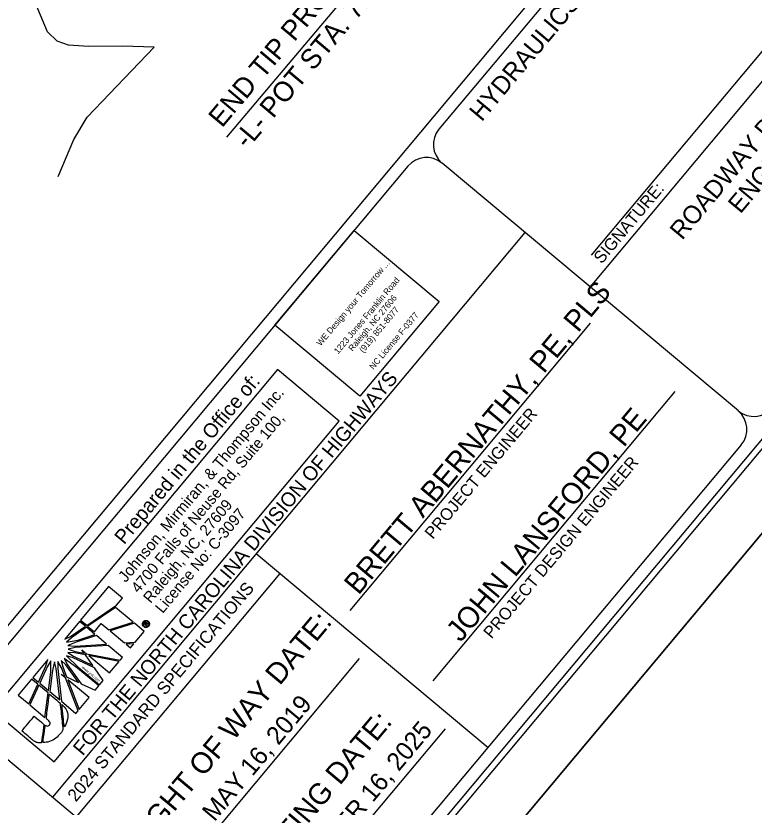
# Model space of a CAD drawing. Extents: x 555292 to 2368606, y 503623 to 1171444.
# Drawn here: x 2361691 to 2363221, y 1163175 to 1164815 of the extents above; entities that cross this region are included whole.
import ezdxf

# ---------------------------------------------------------------- set-up
doc = ezdxf.new("R2010")
doc.units = 0
for name, color, linetype in [('Old_Level_48', 7, 'Continuous'), ('Prop DSN Text', 7, 'Continuous'), ('Prop Horizontal Alignment Station Label', 7, 'Continuous'), ('Sheet Cutting Line CELL', 7, 'Continuous'), ('Sheet Data Field CELL', 7, 'Continuous'), ('Sheet Plot Border Inside CELL', 7, 'Continuous'), ('Sheet Plot Border Outside CELL', 7, 'Continuous'), ('Sheet Title CELL', 7, 'Continuous')]:
    doc.layers.add(name, color=color, linetype=linetype)

msp = doc.modelspace()

# ---------------------------------------------------------------- linework, layer by layer
at = {"layer": 'Old_Level_48'}
msp.add_lwpolyline([(2361778.9, 1164481.9), (2361811.7, 1164558.5), (2361839.3, 1164604.9), (2361978.2, 1164750.1), (2361911.7, 1164752.1), (2361841.9, 1164751.4), (2361800.9, 1164754.1), (2361776.9, 1164762.2), (2361757, 1164781.8), (2361660.4, 1165011.9), (2362007.6, 1164911.3), (2362056.6, 1165270.2), (2361940.1, 1165388.6), (2361913.2, 1165415.1), (2361872.2, 1165436.7), (2361834, 1165456.3)], dxfattribs=at)
at = {"layer": 'Prop DSN Text'}
for p, q in [((2361883.6, 1163632.3), (2361825.6, 1163562.8)), ((2361912.1, 1163608.6), (2361883.6, 1163632.3)), ((2361899.7, 1163593.8), (2361912.1, 1163608.6)), ((2361838.7, 1163551.9), (2361899.7, 1163593.8)), ((2361898.1, 1163589.2), (2361840.7, 1163550.2)), ((2361934.6, 1163558.8), (2361898.1, 1163589.2)), ((2361823.6, 1163560.1), (2361792.8, 1163523.6)), ((2361835.5, 1163550.2), (2361823.6, 1163560.1)), ((2361825.6, 1163562.8), (2361838.3, 1163552.2)), ((2361854.2, 1163538.9), (2361868.4, 1163555.9)), ((2361868.4, 1163555.9), (2361884.2, 1163542.6)), ((2361884.2, 1163542.6), (2361934.6, 1163558.8)), ((2361937.1, 1163556.6), (2361887, 1163540.4)), ((2361957.6, 1163539.5), (2361937.1, 1163556.6)), ((2361955.5, 1163559.6), (2361956.5, 1163558.7)), ((2361956.5, 1163558.7), (2361955.5, 1163559.6)), ((2361956.7, 1163555), (2361958.4, 1163557.1)), ((2361961.8, 1163550.8), (2361956.7, 1163555)), ((2361958.4, 1163557.1), (2361958.7, 1163557.4)), ((2361958.4, 1163557.1), (2361959.4, 1163556.3)), ((2361959.4, 1163556.3), (2361958.4, 1163557.1)), ((2361959.4, 1163556.3), (2361958.6, 1163555.4)), ((2361958.6, 1163555.4), (2361959.8, 1163554.4)), ((2361959.5, 1163556.4), (2361959.4, 1163556.3)), ((2361959.8, 1163554.4), (2361960.6, 1163555.3)), ((2361960.6, 1163555.3), (2361961.5, 1163554.5)), ((2361961.5, 1163554.5), (2361960.6, 1163555.3)), ((2361960.6, 1163555.3), (2361960.6, 1163555.3)), ((2361961.5, 1163554.5), (2361960.8, 1163553.6)), ((2361960.8, 1163553.6), (2361962.7, 1163552)), ((2361961.6, 1163554.6), (2361961.5, 1163554.5)), ((2361804.9, 1163529.2), (2361835.5, 1163550.2)), ((2361838, 1163548.1), (2361806.6, 1163526.3)), ((2361855.3, 1163533.3), (2361838, 1163548.1)), ((2361838.3, 1163552.2), (2361838.7, 1163551.9)), ((2361840.7, 1163550.2), (2361840.9, 1163550)), ((2361840.9, 1163550), (2361854.2, 1163538.9)), ((2361887, 1163540.4), (2361916.5, 1163515.7)), ((2361938.9, 1163517.1), (2361957.6, 1163539.5)), ((2361962.7, 1163552), (2361961.8, 1163550.8)), ((2361965.5, 1163551.2), (2361965.5, 1163551.3)), ((2361965.5, 1163551.2), (2361966.6, 1163550.3)), ((2361966.6, 1163550.3), (2361965.5, 1163551.2)), ((2361966.6, 1163550.4), (2361966.6, 1163550.3)), ((2361792.8, 1163523.6), (2361804.9, 1163529.2)), ((2361806.6, 1163526.3), (2361796.7, 1163517.2)), ((2361796.7, 1163517.2), (2361819.6, 1163521.6)), ((2361858.3, 1163530.8), (2361816.5, 1163517.5)), ((2361819.6, 1163521.6), (2361855.3, 1163533.3)), ((2361879.4, 1163513.1), (2361858.3, 1163530.8)), ((2361816.5, 1163517.5), (2361799.4, 1163510)), ((2361799.4, 1163510), (2361813.9, 1163508.8)), ((2361814.3, 1163506), (2361800.2, 1163502.8)), ((2361813.9, 1163508.8), (2361879.4, 1163513.1)), ((2361882.9, 1163510.3), (2361814.3, 1163506)), ((2361912.5, 1163485.5), (2361882.9, 1163510.3)), ((2361916.5, 1163515.7), (2361938.9, 1163517.1)), ((2361936.2, 1163513.8), (2361919.8, 1163513)), ((2361919.8, 1163513), (2361929, 1163505.2)), ((2361929, 1163505.2), (2361936.2, 1163513.8)), ((2361796.3, 1163489.2), (2361820.9, 1163465.7)), ((2361810.5, 1163484.7), (2361796.3, 1163489.2)), ((2361799.2, 1163495.7), (2361810.7, 1163487.9)), ((2361813, 1163495), (2361799.2, 1163495.7)), ((2361800.2, 1163502.8), (2361814.1, 1163498)), ((2361810.7, 1163487.9), (2361851.3, 1163468.6)), ((2361835.6, 1163490.7), (2361813, 1163495)), ((2361814.1, 1163498), (2361833.2, 1163494.1)), ((2361833.2, 1163494.1), (2361828.1, 1163501.3)), ((2361828.1, 1163501.3), (2361837.7, 1163493.2)), ((2361851.3, 1163468.6), (2361835.6, 1163490.7)), ((2361837.7, 1163493.2), (2361907.7, 1163479.7)), ((2361905.2, 1163477.1), (2361842.5, 1163489.3)), ((2361842.5, 1163489.3), (2361885.5, 1163453.4)), ((2361757.7, 1163481.5), (2361726.6, 1163444.3)), ((2361753.9, 1163468.5), (2361757.7, 1163481.5)), ((2361764.2, 1163478.2), (2361756.5, 1163466.4)), ((2361763.9, 1163455.3), (2361764.2, 1163478.2)), ((2361771.6, 1163476.7), (2361767.5, 1163458.8)), ((2361775.2, 1163462.8), (2361771.6, 1163476.7)), ((2361778.8, 1163477.2), (2361778.2, 1163462.8)), ((2361786, 1163464.3), (2361778.8, 1163477.2)), ((2361785.7, 1163479.5), (2361788.6, 1163465.9)), ((2361795.1, 1163470), (2361785.7, 1163479.5)), ((2361819, 1163463.4), (2361791.7, 1163483.7)), ((2361791.7, 1163483.7), (2361798.5, 1163470.3)), ((2361854.7, 1163463.9), (2361810.5, 1163484.7)), ((2361885.5, 1163453.4), (2361905.2, 1163477.1)), ((2361907.7, 1163479.7), (2361912.5, 1163485.5)), ((2361738.4, 1163434.4), (2361753.9, 1163468.5)), ((2361756.5, 1163466.4), (2361741, 1163432.3)), ((2361758.9, 1163417.3), (2361763.9, 1163455.3)), ((2361767.5, 1163458.8), (2361761.8, 1163414.9)), ((2361782.4, 1163397.7), (2361775.2, 1163462.8)), ((2361778.2, 1163462.8), (2361785.9, 1163394.8)), ((2361792.8, 1163446.9), (2361786, 1163464.3)), ((2361788.6, 1163465.9), (2361796.7, 1163445.2)), ((2361821, 1163433.9), (2361795.1, 1163470)), ((2361798.5, 1163470.3), (2361826.5, 1163431.2)), ((2361863.1, 1163426.6), (2361819, 1163463.4)), ((2361820.9, 1163465.7), (2361865, 1163428.9)), ((2361872.7, 1163438.1), (2361854.7, 1163463.9)), ((2361723.9, 1163440.7), (2361696.3, 1163407.7)), ((2361736.7, 1163430.1), (2361723.9, 1163440.7)), ((2361726.6, 1163444.3), (2361738.4, 1163434.4)), ((2361794.2, 1163443), (2361785.5, 1163450.2)), ((2361785.5, 1163450.2), (2361792.8, 1163446.9)), ((2361820.5, 1163375.2), (2361794.2, 1163443)), ((2361796.7, 1163445.2), (2361821, 1163433.9)), ((2361843.2, 1163402.4), (2361798.9, 1163439)), ((2361798.9, 1163439), (2361822.6, 1163377.8)), ((2361718.2, 1163389.4), (2361736.7, 1163430.1)), ((2361739.1, 1163428.1), (2361720.7, 1163387.3)), ((2361758.2, 1163412.1), (2361739.1, 1163428.1)), ((2361741, 1163432.3), (2361758.9, 1163417.3)), ((2361826.5, 1163431.2), (2361855.5, 1163417.5)), ((2361855.5, 1163417.5), (2361863.1, 1163426.6)), ((2361865, 1163428.9), (2361872.7, 1163438.1)), ((2361696.3, 1163407.7), (2361718.2, 1163389.4)), ((2361751.6, 1163361.5), (2361758.2, 1163412.1)), ((2361761.8, 1163414.9), (2361782.4, 1163397.7)), ((2361785.9, 1163394.8), (2361815.9, 1163369.7)), ((2361822.6, 1163377.8), (2361843.2, 1163402.4)), ((2361720.7, 1163387.3), (2361751.6, 1163361.5)), ((2361815.9, 1163369.7), (2361820.5, 1163375.2))]:
    msp.add_line(p, q, dxfattribs=at)
for points in [[(2362568.3, 1164223), (2362403.9, 1164026.5), (2362228, 1164173.7), (2362392.4, 1164370.2)], [(2361770.7, 1163269.5), (2362361.1, 1163975.3), (2362233.7, 1164081.9), (2361643.3, 1163376.1)]]:
    msp.add_lwpolyline(points, close=True, dxfattribs=at)
for points in [[(2361883.6, 1163632.3), (2361825.6, 1163562.8), (2361838.3, 1163552.2), (2361838.7, 1163551.9), (2361899.7, 1163593.8), (2361912.1, 1163608.6), (2361883.6, 1163632.3)], [(2361840.7, 1163550.2), (2361840.9, 1163550), (2361854.2, 1163538.9), (2361868.4, 1163555.9), (2361884.2, 1163542.6), (2361934.6, 1163558.8), (2361898.1, 1163589.2), (2361840.7, 1163550.2)], [(2361804.9, 1163529.2), (2361835.5, 1163550.2), (2361823.6, 1163560.1), (2361792.8, 1163523.6), (2361804.9, 1163529.2)], [(2361887, 1163540.4), (2361916.5, 1163515.7), (2361938.9, 1163517.1), (2361957.6, 1163539.5), (2361937.1, 1163556.6), (2361887, 1163540.4), (2361887, 1163540.4)], [(2361964.1, 1163556.1), (2361964.4, 1163555.9), (2361964.6, 1163555.7), (2361964.8, 1163555.6), (2361965.5, 1163555.3), (2361964.6, 1163554.2)], [(2361796.7, 1163517.2), (2361819.6, 1163521.6), (2361855.3, 1163533.3), (2361838, 1163548.1), (2361806.6, 1163526.3), (2361796.7, 1163517.2)], [(2361799.4, 1163510), (2361813.9, 1163508.8), (2361879.4, 1163513.1), (2361858.3, 1163530.8), (2361816.5, 1163517.5), (2361799.4, 1163510)], [(2361800.2, 1163502.8), (2361814.1, 1163498), (2361833.2, 1163494.1), (2361828.1, 1163501.3), (2361837.7, 1163493.2), (2361907.7, 1163479.7), (2361912.5, 1163485.5), (2361882.9, 1163510.3), (2361814.3, 1163506), (2361800.2, 1163502.8)], [(2361929, 1163505.2), (2361929, 1163505.2), (2361936.2, 1163513.8), (2361919.8, 1163513), (2361929, 1163505.2)], [(2361796.3, 1163489.2), (2361820.9, 1163465.7), (2361865, 1163428.9), (2361872.7, 1163438.1), (2361854.7, 1163463.9), (2361810.5, 1163484.7), (2361796.3, 1163489.2)], [(2361799.2, 1163495.7), (2361810.7, 1163487.9), (2361851.3, 1163468.6), (2361835.6, 1163490.7), (2361813, 1163495), (2361799.2, 1163495.7)], [(2361885.5, 1163453.4), (2361905.2, 1163477.1), (2361842.5, 1163489.3), (2361885.5, 1163453.4)], [(2361753.9, 1163468.5), (2361757.7, 1163481.5), (2361726.6, 1163444.3), (2361738.4, 1163434.4), (2361753.9, 1163468.5)], [(2361741, 1163432.3), (2361758.9, 1163417.3), (2361763.9, 1163455.3), (2361764.2, 1163478.2), (2361756.5, 1163466.4), (2361741, 1163432.3)], [(2361761.8, 1163414.9), (2361782.4, 1163397.7), (2361775.2, 1163462.8), (2361771.6, 1163476.7), (2361767.5, 1163458.8), (2361761.8, 1163414.9)], [(2361778.8, 1163477.2), (2361778.2, 1163462.8), (2361785.9, 1163394.8), (2361815.9, 1163369.7), (2361820.5, 1163375.2), (2361794.2, 1163443), (2361785.5, 1163450.2), (2361792.8, 1163446.9), (2361786, 1163464.3), (2361778.8, 1163477.2)], [(2361785.7, 1163479.5), (2361788.6, 1163465.9), (2361796.7, 1163445.2), (2361821, 1163433.9), (2361795.1, 1163470), (2361785.7, 1163479.5)], [(2361798.5, 1163470.3), (2361826.5, 1163431.2), (2361855.5, 1163417.5), (2361863.1, 1163426.6), (2361819, 1163463.4), (2361791.7, 1163483.7), (2361798.5, 1163470.3)], [(2361718.2, 1163389.4), (2361736.7, 1163430.1), (2361723.9, 1163440.7), (2361696.3, 1163407.7), (2361718.2, 1163389.4)], [(2361822.6, 1163377.8), (2361843.2, 1163402.4), (2361798.9, 1163439), (2361822.6, 1163377.8)], [(2361751.6, 1163361.5), (2361758.2, 1163412.1), (2361739.1, 1163428.1), (2361720.7, 1163387.3), (2361751.6, 1163361.5)]]:
    msp.add_lwpolyline(points, dxfattribs=at)
for points, degree in [([(2361966.6, 1163550.3), (2361965.3, 1163548.8), (2361963.6, 1163547.9), (2361961.6, 1163547.7), (2361959.6, 1163547.5), (2361957.9, 1163548.1), (2361956.3, 1163549.4), (2361954.7, 1163550.7), (2361953.9, 1163552.4), (2361953.8, 1163554.3), (2361953.6, 1163556.3), (2361954.2, 1163558), (2361955.5, 1163559.6)], 3), ([(2361956.5, 1163558.7), (2361955.5, 1163557.5), (2361955, 1163556.1), (2361955.1, 1163554.5), (2361955.3, 1163552.9), (2361956, 1163551.5), (2361957.2, 1163550.5), (2361958.5, 1163549.4), (2361959.9, 1163549), (2361961.5, 1163549.1), (2361963.1, 1163549.3), (2361964.4, 1163550), (2361965.5, 1163551.2)], 3), ([(2361955.5, 1163559.6), (2361956.8, 1163561.2), (2361958.4, 1163562), (2361960.4, 1163562.2), (2361962.3, 1163562.5), (2361964.1, 1163561.9), (2361965.7, 1163560.6)], 3), ([(2361965.5, 1163551.3), (2361966.5, 1163552.5), (2361967, 1163553.9), (2361966.9, 1163555.5), (2361966.7, 1163557.1), (2361966, 1163558.5), (2361964.8, 1163559.5), (2361963.5, 1163560.6), (2361962, 1163561), (2361960.4, 1163560.9), (2361958.9, 1163560.7), (2361957.6, 1163560), (2361956.5, 1163558.7)], 3), ([(2361958.7, 1163557.4), (2361959.8, 1163558.7), (2361960.8, 1163558.9), (2361961.8, 1163558.1), (2361962.3, 1163557.7), (2361962.5, 1163557.2), (2361962.4, 1163556.6)], 3), ([(2361960.6, 1163555.3), (2361961.3, 1163556.1), (2361961.3, 1163556.6), (2361960.9, 1163557), (2361960.6, 1163557.3), (2361960.1, 1163557.1), (2361959.5, 1163556.4)], 3), ([(2361962.5, 1163555.3), (2361962.3, 1163555.2), (2361961.9, 1163555), (2361961.6, 1163554.6)], 2), ([(2361962.4, 1163556.6), (2361962.9, 1163556.7), (2361963.5, 1163556.6), (2361964.1, 1163556.1)], 2), ([(2361964.6, 1163554.2), (2361964.2, 1163554.3), (2361963.9, 1163554.4), (2361963.5, 1163554.7), (2361963, 1163555.1), (2361962.7, 1163555.3), (2361962.5, 1163555.3)], 3), ([(2361965.7, 1163560.6), (2361967.3, 1163559.3), (2361968.1, 1163557.7), (2361968.3, 1163555.7), (2361968.5, 1163553.7), (2361967.9, 1163551.9), (2361966.6, 1163550.4)], 3), ([(2361761, 1163345.6), (2361759.3, 1163343.7), (2361756.8, 1163342.9), (2361752.6, 1163345.2), (2361752.6, 1163345.2), (2361747.4, 1163309.2), (2361747.4, 1163309.2), (2361761.2, 1163310.1), (2361775.6, 1163318), (2361783.8, 1163327.9), (2361786, 1163330.4), (2361787.4, 1163332.6), (2361789.1, 1163335.8), (2361789.1, 1163335.8), (2361783.2, 1163391.2), (2361783.2, 1163391.2), (2361783.2, 1163391.2), (2361760.9, 1163409.8), (2361760.9, 1163409.8), (2361760.9, 1163409.8), (2361754.4, 1163359.2), (2361754.4, 1163359.2), (2361762.7, 1163352.2), (2361763.2, 1163348.4), (2361761, 1163345.6)], 3), ([(2361761, 1163345.6), (2361759.3, 1163343.7), (2361756.8, 1163342.9), (2361752.6, 1163345.2), (2361752.6, 1163345.2), (2361747.4, 1163309.2), (2361747.4, 1163309.2), (2361761.2, 1163310.1), (2361775.6, 1163318), (2361783.8, 1163327.9), (2361786, 1163330.4), (2361787.4, 1163332.6), (2361789.1, 1163335.8), (2361789.1, 1163335.8), (2361783.2, 1163391.2), (2361783.2, 1163391.2), (2361783.2, 1163391.2), (2361760.9, 1163409.8), (2361760.9, 1163409.8), (2361760.9, 1163409.8), (2361754.4, 1163359.2), (2361754.4, 1163359.2), (2361762.7, 1163352.2), (2361763.2, 1163348.4), (2361761, 1163345.6)], 3), ([(2361786.7, 1163388.3), (2361786.7, 1163388.3), (2361791.8, 1163340.4), (2361791.8, 1163340.4), (2361799.2, 1163355.6), (2361801.3, 1163375.1), (2361786.7, 1163388.3)], 3), ([(2361729.5, 1163363.9), (2361729.5, 1163363.9), (2361703.9, 1163333.3), (2361703.9, 1163333.3), (2361703.9, 1163333.3), (2361723.1, 1163317.3), (2361723.1, 1163317.3), (2361723.1, 1163317.3), (2361725.1, 1163315.6), (2361725.1, 1163315.6), (2361731.1, 1163310.6), (2361737.5, 1163308.6), (2361744.4, 1163308.8), (2361744.4, 1163308.8), (2361750.1, 1163346.7), (2361749.7, 1163347), (2361749.7, 1163347), (2361729.5, 1163363.9), (2361729.5, 1163363.9)], 3)]:
    msp.add_open_spline(points, degree=degree, dxfattribs=at)
at = {"layer": 'Prop Horizontal Alignment Station Label'}
msp.add_line((2362128.7, 1164563.4), (2362659.7, 1165192.7), dxfattribs=at)
at = {"layer": 'Sheet Cutting Line CELL'}
msp.add_line((2359251.2, 1158978), (2364653.4, 1165436.5), dxfattribs=at)
at = {"layer": 'Sheet Plot Border Inside CELL'}
msp.add_lwpolyline([(2359232.5, 1159130.5), (2364578.6, 1165521.9), (2360532, 1168906.6), (2355185.9, 1162515.2)], close=True, dxfattribs=at)
at = {"layer": 'Sheet Plot Border Outside CELL'}
msp.add_line((2364704.7, 1165497.9), (2359251.2, 1158978), dxfattribs=at)
at = {"layer": 'Sheet Title CELL'}
for p, q in [((2359196.5, 1160588.2), (2363751.8, 1166034.2)), ((2362568, 1164579.9), (2363208.9, 1165346.1)), ((2362878.1, 1164249.5), (2363586, 1165095.8)), ((2362884, 1164318.8), (2363346.8, 1164872.1)), ((2363188, 1163996.2), (2362574.3, 1164509.5)), ((2361589.6, 1163410.2), (2362503.8, 1164503.2)), ((2362746, 1164365.9), (2361767.5, 1163196.2)), ((2362384.2, 1163582.8), (2362882, 1164177.8)), ((2362555.7, 1163437.1), (2363056.9, 1164036.4)), ((2362189.5, 1163700.7), (2362669.8, 1163298.9)), ((2362238.4, 1163659.8), (2361816.4, 1163155.3)), ((2362116.8, 1163514.5), (2362116.8, 1163514.5)), ((2362402.7, 1163483.3), (2362037.7, 1163047.1)), ((2361595.9, 1163339.8), (2362209.5, 1162826.5)), ((2362580.5, 1163337.9), (2362215.6, 1162901.6)), ((2362220.2, 1163265.1), (2362220.2, 1163265.1))]:
    msp.add_line(p, q, dxfattribs=at)
for points in [[(2359748.8, 1159767.7), (2364496.6, 1165443.8)], [(2362279.9, 1162832.8), (2363194.2, 1163925.8)]]:
    msp.add_lwpolyline(points, dxfattribs=at)
for centre, start, end in [((2362606.2, 1164548), 140.0895, 230.0895), ((2362542, 1164471.3), 50.0895, 140.0895), ((2363219.8, 1164034.8), 230.0895, 320.0895), ((2363155.7, 1163958), 320.0895, 50.0895)]:
    msp.add_arc(centre, 50, start, end, dxfattribs=at)

# ---------------------------------------------------------------- texts
at = {"layer": 'Prop DSN Text'}
for s, height, rotation, p in [('WE Design your Tomorrow ...', 12.808, 50.0706, (2362322.8, 1164129.8)), ('1223 Jones Franklin Road', 12.808, 50.0706, (2362359, 1164113.2)), ('Raleigh, NC 27606', 12.808, 50.0706, (2362388.8, 1164118.8)), ('(919) 851-8077', 12.808, 50.0706, (2362411.1, 1164115.6)), ('NC License F-0377', 12.808, 50.0706, (2362432.2, 1164080.9)), ('Johnson, Mirmiran, & Thompson Inc.', 23.511, 50.0895, (2361919.1, 1163639.4)), ('4700 Falls of Neuse Rd, Suite 100, ', 22.84, 50.0895, (2361945.5, 1163617.3)), ('Raleigh, NC, 27609', 22.84, 50.0895, (2361970.6, 1163596.4)), ('License No: C-3097', 22.84, 50.0895, (2361995.6, 1163575.4)), ('www.jmt.com', 5.71, 320.0895, (2361827.3, 1163464.2))]:
    msp.add_text(s, height=height, rotation=rotation, dxfattribs=at).set_placement(p)
at = {"layer": 'Prop Horizontal Alignment Station Label'}
for s, p in [('END TIP PROJECT R-5863', (2362118.5, 1164581.2)), ('-L- POT STA. 72+65.00', (2362171.2, 1164537))]:
    msp.add_text(s, height=41.248, rotation=49.9796, dxfattribs=at).set_placement(p)
at = {"layer": 'Sheet Data Field CELL'}
for s, p in [('BRETT ABERNATHY, PE, PLS', (2362401.2, 1163613.2)), ('JOHN LANSFORD, PE', (2362612.7, 1163515.3))]:
    msp.add_text(s, height=43.75, rotation=50.0895, dxfattribs=at).set_placement(p)
at = {"layer": 'Sheet Title CELL'}
for s, height, p in [(' HYDRAULICS ENGINEER', 37.5, (2362647.4, 1164583.2)), ('ROADWAY DESIGN', 37.497, (2363071.5, 1164348.5)), ('ENGINEER', 37.5, (2363192.1, 1164403)), ('SIGNATURE:', 25, (2362905, 1164299.5)), ('FOR THE NORTH CAROLINA DIVISION OF HIGHWAYS', 29.715, (2361830, 1163280.3)), ('Prepared in the Office of:', 29.715, (2361915.8, 1163717.9)), ('PROJECT ENGINEER', 24.997, (2362555.2, 1163728.9)), ('PROJECT DESIGN ENGINEER', 24.997, (2362676.7, 1163522.9)), ('2024 STANDARD SPECIFICATIONS', 26, (2361816, 1163184.9)), ('RIGHT OF WAY DATE: ', 43.749, (2361952.3, 1163084.3)), ('MAY 16, 2019', 37.5, (2362102.9, 1163143.9)), ('LETTING DATE:', 43.749, (2362193.6, 1163017.1)), ('SEPTEMBER 16, 2025', 37.5, (2362223.5, 1162935.9))]:
    msp.add_text(s, height=height, rotation=50.0895, dxfattribs=at).set_placement(p)

doc.saveas('drawing.dxf')
